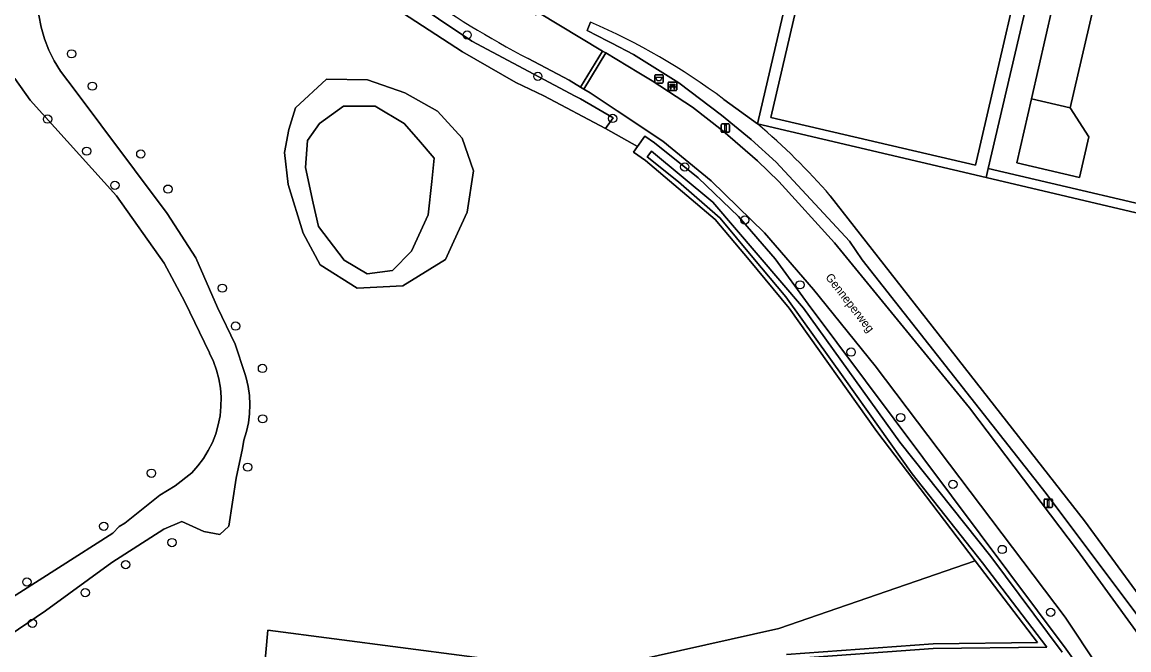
# Model space of a CAD drawing. Extents: x 160203 to 161530, y 379528 to 381797.
# Drawn here: x 160837.8 to 160969.1, y 381364.6 to 381439 of the extents above; entities that cross this region are included whole.
import ezdxf

# ---------------------------------------------------------------- set-up
doc = ezdxf.new("R2010")
doc.units = 0
for name, color, linetype in [('IMGEO_Afvalbak', 7, 'Continuous'), ('IMGEO_Bank', 7, 'Continuous'), ('IMGEO_Berm_groen', 7, 'Continuous'), ('IMGEO_Boom', 7, 'Continuous'), ('IMGEO_Grasland_agrarisch', 7, 'Continuous'), ('IMGEO_Grasland_overig', 7, 'Continuous'), ('IMGEO_Groenvoorziening', 7, 'Continuous'), ('IMGEO_Hek', 7, 'Continuous'), ('IMGEO_Lichtmast', 7, 'Continuous'), ('IMGEO_Loofbos', 7, 'Continuous'), ('IMGEO_Meer_plas_ven_vijver', 7, 'Continuous'), ('IMGEO_Oever', 7, 'Continuous'), ('IMGEO_Openbare_ruimte_label', 7, 'Continuous'), ('IMGEO_Rijbaan_lokaal_gesloten', 7, 'Continuous'), ('IMGEO_Waterloop', 7, 'Continuous')]:
    doc.layers.add(name, color=color, linetype=linetype)

msp = doc.modelspace()

# ---------------------------------------------------------------- linework, layer by layer
at = {"layer": 'IMGEO_Afvalbak'}
for p, q in [((160912.86, 381431.87), (160912.86, 381432.67)), ((160912.86, 381432.67), (160912.86, 381431.87)), ((160912.96, 381432.77), (160913.75, 381432.77)), ((160913.75, 381432.77), (160912.96, 381432.77)), ((160913.85, 381432.67), (160913.85, 381431.87)), ((160913.85, 381431.87), (160913.85, 381432.67)), ((160913.75, 381431.77), (160912.96, 381431.77)), ((160912.96, 381431.77), (160913.75, 381431.77))]:
    msp.add_line(p, q, dxfattribs=at)
msp.add_lwpolyline([(160913, 381432.49), (160913.71, 381432.49), (160913.56, 381432.02), (160913.15, 381432.02), (160913, 381432.49)], dxfattribs=at)
for centre, start, end in [((160912.96, 381432.67), 90, 180), ((160912.96, 381432.67), 90, 180), ((160912.96, 381431.87), 180, 270), ((160912.96, 381431.87), 180, 270), ((160913.75, 381432.67), 0, 90), ((160913.75, 381432.67), 360, 90), ((160913.75, 381431.87), 270, 0), ((160913.75, 381431.87), 270, 0)]:
    msp.add_arc(centre, 0.1, start, end, dxfattribs=at)
at = {"layer": 'IMGEO_Bank'}
for p, q in [((160914.53, 381431.88), (160915.37, 381431.88)), ((160915.37, 381431.88), (160914.53, 381431.88)), ((160914.46, 381430.96), (160914.46, 381431.8)), ((160914.46, 381431.8), (160914.46, 381430.96)), ((160915.38, 381430.89), (160914.54, 381430.89)), ((160914.54, 381430.89), (160915.38, 381430.89)), ((160915.16, 381431.28), (160914.76, 381431.28)), ((160914.77, 381431.39), (160914.77, 381431.5)), ((160914.81, 381431.5), (160914.81, 381431.39)), ((160915.1, 381431.5), (160914.82, 381431.5)), ((160914.82, 381431.39), (160915.1, 381431.39)), ((160915.11, 381431.39), (160915.11, 381431.5)), ((160915.15, 381431.5), (160915.15, 381431.39)), ((160915.46, 381431.81), (160915.46, 381430.97)), ((160915.46, 381430.97), (160915.46, 381431.81))]:
    msp.add_line(p, q, dxfattribs=at)
for points in [[(160914.71, 381431.28), (160914.56, 381431.28), (160914.68, 381431.39), (160914.76, 381431.39)], [(160914.76, 381431.5), (160914.68, 381431.5), (160914.68, 381431.66), (160915.24, 381431.66), (160915.24, 381431.5), (160915.16, 381431.5)], [(160914.76, 381431.28), (160914.76, 381431.07), (160914.71, 381431.07), (160914.71, 381431.28)], [(160915.16, 381431.39), (160915.24, 381431.39), (160915.35, 381431.28), (160915.21, 381431.28)], [(160915.21, 381431.28), (160915.21, 381431.07), (160915.16, 381431.07), (160915.16, 381431.28)]]:
    msp.add_lwpolyline(points, dxfattribs=at)
for centre, radius, start, end in [((160914.54, 381431.81), 0.0779, 92.4484, 184.2845), ((160914.54, 381431.81), 0.0779, 92.4484, 184.2845), ((160915.38, 381431.81), 0.0779, 2.4484, 94.2845), ((160915.38, 381431.81), 0.0779, 2.4484, 94.2845), ((160914.54, 381430.96), 0.0779, 182.4484, 274.2845), ((160914.54, 381430.96), 0.0779, 182.4484, 274.2845), ((160914.71, 381431.28), 0.00671, 2.8957, 87.1043), ((160914.76, 381431.5), 0.00671, 2.8957, 87.1043), ((160914.76, 381431.39), 0.00671, 272.8957, 357.1043), ((160914.76, 381431.28), 0.00671, 92.8957, 177.1043), ((160914.82, 381431.5), 0.00671, 92.8957, 177.1043), ((160914.82, 381431.39), 0.00671, 182.8957, 267.1043), ((160915.1, 381431.5), 0.00671, 2.8957, 87.1043), ((160915.1, 381431.39), 0.00671, 272.8957, 357.1043), ((160915.16, 381431.5), 0.00671, 92.8957, 177.1043), ((160915.16, 381431.39), 0.00671, 182.8957, 267.1043), ((160915.16, 381431.28), 0.00671, 2.8957, 87.1043), ((160915.21, 381431.28), 0.00671, 92.8957, 177.1043), ((160915.38, 381430.96), 0.0779, 272.4484, 4.2845), ((160915.38, 381430.96), 0.0779, 272.4484, 4.2845)]:
    msp.add_arc(centre, radius, start, end, dxfattribs=at)
at = {"layer": 'IMGEO_Berm_groen'}
for points in [[(160879.19, 381444.82), (160891.17, 381436.75), (160903.43, 381430.24), (160903.82, 381430.04), (160904.06, 381429.91), (160907.93, 381427.65), (160907.02, 381426.38), (160910.8, 381424.24), (160911.68, 381425.48), (160912.82, 381424.67), (160918, 381420.53), (160922.79, 381415.94), (160927.15, 381410.94), (160931.05, 381405.58), (160961.66, 381364.64), (160973.27, 381348.35)], [(160993, 381294.71), (160992.52, 381299.99), (160991.71, 381305.79), (160990.96, 381309.38), (160989.45, 381315.12), (160986.02, 381325.95), (160981.64, 381336.44), (160977.58, 381344.32), (160969.51, 381356.48), (160969.3, 381356.8), (160961.55, 381368.47), (160938.99, 381398.24), (160931.67, 381407.29), (160925.89, 381414), (160919.55, 381420.17), (160913.8, 381424.9), (160908.4, 381428.48), (160905.18, 381430.61), (160904.44, 381431.06), (160904.06, 381431.29), (160902.71, 381432.11), (160897.85, 381434.68)]]:
    msp.add_lwpolyline(points, dxfattribs=at)
msp.add_arc((160952.12, 381538.44), 117.1, 234.6618, 242.3896, dxfattribs=at)
at = {"layer": 'IMGEO_Boom'}
for centre in [(160890.61, 381437.48), (160843.69, 381435.24), (160846.15, 381431.41), (160898.99, 381432.57), (160840.84, 381427.5), (160907.87, 381427.58), (160845.47, 381423.7), (160851.9, 381423.37), (160916.42, 381421.83), (160848.83, 381419.65), (160855.12, 381419.2), (160923.54, 381415.53), (160930.09, 381407.85), (160861.57, 381407.46), (160863.14, 381402.96), (160936.15, 381399.88), (160866.33, 381397.94), (160942.03, 381392.12), (160866.36, 381391.97), (160853.16, 381385.52), (160864.58, 381386.24), (160948.22, 381384.2), (160847.51, 381379.23), (160855.6, 381377.3), (160954.07, 381376.48), (160850.11, 381374.68), (160838.39, 381372.62), (160845.31, 381371.36), (160959.82, 381369.03), (160839.05, 381367.73)]:
    msp.add_circle(centre, 0.489, dxfattribs=at)
at = {"layer": 'IMGEO_Grasland_agrarisch'}
for points in [[(160910.26, 381363.22), (160927.59, 381367.12), (160950.85, 381375.14), (160939.19, 381390.45), (160928.82, 381405.1), (160924.07, 381410.83), (160920.01, 381415.59), (160911.77, 381422.61), (160910.35, 381423.6), (160910.8, 381424.24), (160907.02, 381426.38), (160899.71, 381430.26), (160896.4, 381431.86), (160890.07, 381435.47), (160878.99, 381442.69)], [(160839.8, 381439.81), (160840.07, 381438.4), (160840.47, 381437.02), (160840.99, 381435.68), (160841.63, 381434.4), (160842.38, 381433.17), (160843.23, 381432.02), (160843.27, 381431.98), (160855.03, 381416.33), (160858.42, 381411.04), (160860.99, 381405.15), (160863.09, 381400.82), (160864.24, 381397.36), (160864.41, 381396.83), (160864.65, 381395.79), (160864.8, 381394.72), (160864.85, 381393.65), (160864.81, 381392.57), (160864.67, 381391.51), (160864.43, 381390.46), (160864.11, 381389.43), (160863.95, 381388.43), (160863.2, 381384.92), (160862.36, 381379.25), (160861.29, 381378.25), (160859.39, 381378.61), (160856.75, 381379.8), (160854.63, 381378.9), (160848.45, 381374.92), (160840.6, 381369.21), (160835.29, 381365.61)], [(160861.25, 381302.95), (160866.96, 381366.91), (160898.45, 381362.81)]]:
    msp.add_lwpolyline(points, dxfattribs=at)
msp.add_lwpolyline([(160877.58, 381407.45), (160873.19, 381410.22), (160871.16, 381413.96), (160869.36, 381419.74), (160868.94, 381423.53), (160869.45, 381426.26), (160870.24, 381428.85), (160873.93, 381432.22), (160878.78, 381432.17), (160883.22, 381430.6), (160887.1, 381428.43), (160890.01, 381425.24), (160891.35, 381421.36), (160890.61, 381416.46), (160889.04, 381413.04), (160888.04, 381410.87), (160882.99, 381407.73)], close=True, dxfattribs=at)
at = {"layer": 'IMGEO_Grasland_overig'}
msp.add_lwpolyline([(160887, 381511.65), (160943.21, 381498.82), (160926.61, 381427.71), (160950.89, 381422.03), (160966.02, 381487.2), (160966.83, 381487.02), (160967.33, 381489.23), (160968.8, 381488.86), (160972.12, 381488.02), (160973.76, 381493.85), (160983.38, 381535.9)], dxfattribs=at)
at = {"layer": 'IMGEO_Groenvoorziening'}
for points in [[(161150.15, 381500), (161152.01, 381508.05), (161153.71, 381515.38), (161141.46, 381516.56), (161125.47, 381518.11), (161084.45, 381527.5), (161000, 381546.84), (160993.38, 381548.35), (160986.4, 381549.95), (160985.95, 381548.01), (160992.01, 381546.65), (161000, 381544.86), (161087.73, 381524.31), (161123.21, 381516.23), (161094.22, 381388.52), (161000, 381410.48), (160979.1, 381415.39), (160952.41, 381421.66), (160952.15, 381420.57), (161000, 381409.32), (161095.64, 381387.19), (161107.24, 381437.71), (161118.58, 381435.09), (161134.28, 381431.47)], [(160968.89, 381457.97), (160964.18, 381459.05), (160957.55, 381429.91), (160962.15, 381428.85)], [(160957.55, 381429.91), (160955.81, 381422.31), (160963.25, 381420.56), (160964.36, 381425.4), (160962.15, 381428.85)]]:
    msp.add_lwpolyline(points, close=True, dxfattribs=at)
for points in [[(160932.03, 381500), (160941.58, 381497.82), (160925.05, 381426.94), (160952.15, 381420.57), (160952.41, 381421.66), (160967.65, 381486.84), (160966.83, 381487.02), (160966.02, 381487.2), (160950.89, 381422.03), (160926.61, 381427.71), (160943.21, 381498.82), (160887, 381511.65)], [(160899, 381440.18), (160906.67, 381435.56), (160907.05, 381435.34), (160910.97, 381432.97), (160912.55, 381432.02), (160917.33, 381428.91), (160920.95, 381426.1), (160925.03, 381422.57), (160927.57, 381420.1), (160934.19, 381412.82), (160950.18, 381393.29), (160963.01, 381376.35), (160971.37, 381364.8)], [(160974.18, 381363.23), (160959.28, 381383.1), (160937.45, 381410.82), (160935.96, 381413.05), (160927.26, 381422.41), (160924.3, 381425.07), (160920.79, 381427.97), (160915.73, 381431.81), (160910.35, 381435.18), (160907.77, 381436.49), (160907.29, 381436.74), (160904.84, 381437.99), (160905.25, 381439)], [(160835.69, 381370.18), (160848.57, 381378.42), (160849.33, 381379.2), (160850, 381379.59), (160854.15, 381382.93), (160855.98, 381384.02), (160857.95, 381385.57), (160858.68, 381386.39), (160859.33, 381387.27), (160859.9, 381388.2), (160860.39, 381389.18), (160860.79, 381390.2), (160861.09, 381391.26), (160861.3, 381392.33), (160861.41, 381393.42), (160861.43, 381394.52), (160861.34, 381395.61), (160861.16, 381396.69), (160860.89, 381397.75), (160860.52, 381398.78), (160860.06, 381399.77), (160860.05, 381399.8), (160857.13, 381405.83), (160854.69, 381410.43), (160849.02, 381418.42), (160838.77, 381429.76), (160836.95, 381432.33)]]:
    msp.add_lwpolyline(points, dxfattribs=at)
at = {"layer": 'IMGEO_Hek'}
for points in [[(160932.03, 381500), (160941.58, 381497.82), (160925.05, 381426.94)], [(160952.41, 381421.66), (160967.65, 381486.84)], [(160925.05, 381426.94), (160952.15, 381420.57)], [(160952.15, 381420.57), (160952.41, 381421.66)], [(160952.15, 381420.57), (161000, 381409.32)]]:
    msp.add_lwpolyline(points, dxfattribs=at)
at = {"layer": 'IMGEO_Lichtmast'}
for p, q in [((160920.74, 381426.04), (160920.74, 381426.83)), ((160920.74, 381426.83), (160920.74, 381426.04)), ((160920.84, 381426.93), (160921.63, 381426.93)), ((160921.63, 381426.93), (160920.84, 381426.93)), ((160921.73, 381426.83), (160921.73, 381426.04)), ((160921.73, 381426.04), (160921.73, 381426.83)), ((160921.63, 381425.94), (160920.84, 381425.94)), ((160920.84, 381425.94), (160921.63, 381425.94)), ((160959.03, 381381.56), (160959.03, 381382.36)), ((160959.03, 381382.36), (160959.03, 381381.56)), ((160959.13, 381382.46), (160959.92, 381382.46)), ((160959.92, 381382.46), (160959.13, 381382.46)), ((160960.02, 381382.36), (160960.02, 381381.56)), ((160960.02, 381381.56), (160960.02, 381382.36)), ((160959.92, 381381.46), (160959.13, 381381.46)), ((160959.13, 381381.46), (160959.92, 381381.46))]:
    msp.add_line(p, q, dxfattribs=at)
for points in [[(160921.16, 381426.81), (160921.31, 381426.81), (160921.31, 381426.06), (160921.16, 381426.06), (160921.16, 381426.81)], [(160959.45, 381382.34), (160959.6, 381382.34), (160959.6, 381381.59), (160959.45, 381381.59), (160959.45, 381382.34)]]:
    msp.add_lwpolyline(points, dxfattribs=at)
for centre, start, end in [((160920.84, 381426.83), 90, 180), ((160920.84, 381426.83), 90, 180), ((160921.63, 381426.83), 0, 90), ((160921.63, 381426.83), 360, 90), ((160920.84, 381426.04), 180, 270), ((160920.84, 381426.04), 180, 270), ((160921.63, 381426.04), 270, 0), ((160921.63, 381426.04), 270, 0), ((160959.13, 381382.36), 90, 180), ((160959.13, 381382.36), 90, 180), ((160959.92, 381382.36), 0, 90), ((160959.92, 381382.36), 360, 90), ((160959.13, 381381.56), 180, 270), ((160959.13, 381381.56), 180, 270), ((160959.92, 381381.56), 270, 0), ((160959.92, 381381.56), 270, 0)]:
    msp.add_arc(centre, 0.1, start, end, dxfattribs=at)
at = {"layer": 'IMGEO_Loofbos'}
for points in [[(160921.04, 381429.84), (160925.05, 381426.94), (160941.58, 381497.82)], [(161000, 381409.32), (160952.15, 381420.57), (160925.05, 381426.94)], [(160933.67, 381418.42), (160963.83, 381379.86), (160979.61, 381358.32), (160978.48, 381357.15), (160978.95, 381356.53), (160995.18, 381359.02), (161012.13, 381363.59), (161027.65, 381369.06), (161045.06, 381375.03), (161050.48, 381376.91), (161056.73, 381379.07)], [(160928.47, 381364.02), (160945.87, 381365.3), (160958.24, 381365.43), (160950.85, 381375.14), (160927.59, 381367.12), (160910.26, 381363.22)], [(160898.45, 381362.81), (160866.96, 381366.91), (160861.25, 381302.95)]]:
    msp.add_lwpolyline(points, dxfattribs=at)
for points in [[(160972.12, 381488.02), (160968.8, 381488.86), (160968.27, 381486.71), (160967.65, 381486.84), (160952.41, 381421.66), (160979.1, 381415.39), (160992.22, 381474.79), (160970.08, 381480.72)], [(160962.15, 381428.85), (160964.36, 381425.4), (160963.25, 381420.56), (160955.81, 381422.31), (160957.55, 381429.91), (160964.18, 381459.05), (160968.89, 381457.97)]]:
    msp.add_lwpolyline(points, close=True, dxfattribs=at)
for centre, radius, start, end in [((160875.24, 381369.02), 76.14, 53.014, 66.7814), ((160874.43, 381367.06), 78.4, 40.9191, 49.7892)]:
    msp.add_arc(centre, radius, start, end, dxfattribs=at)
at = {"layer": 'IMGEO_Meer_plas_ven_vijver'}
msp.add_lwpolyline([(160879.71, 381429.03), (160875.96, 381429.03), (160873.1, 381427), (160871.67, 381424.96), (160871.44, 381421.78), (160872.36, 381417.52), (160872.96, 381414.75), (160876.01, 381410.78), (160878.74, 381409.16), (160881.74, 381409.57), (160884, 381411.84), (160885.99, 381416.14), (160886.41, 381420.11), (160886.7, 381422.86), (160884.84, 381425.06), (160883.13, 381427)], close=True, dxfattribs=at)
at = {"layer": 'IMGEO_Oever'}
for points in [[(160878.78, 381432.17), (160873.93, 381432.22), (160870.24, 381428.85), (160869.45, 381426.26), (160868.94, 381423.53), (160869.36, 381419.74), (160871.16, 381413.96), (160873.19, 381410.22), (160877.58, 381407.45), (160882.99, 381407.73), (160888.04, 381410.87), (160889.04, 381413.04), (160890.61, 381416.46), (160891.35, 381421.36), (160890.01, 381425.24), (160887.1, 381428.43), (160883.22, 381430.6)], [(160879.71, 381429.03), (160883.13, 381427), (160884.84, 381425.06), (160886.7, 381422.86), (160886.41, 381420.11), (160885.99, 381416.14), (160884, 381411.84), (160881.74, 381409.57), (160878.74, 381409.16), (160876.01, 381410.78), (160872.96, 381414.75), (160872.36, 381417.52), (160871.44, 381421.78), (160871.67, 381424.96), (160873.1, 381427), (160875.96, 381429.03)]]:
    msp.add_lwpolyline(points, close=True, dxfattribs=at)
for points in [[(160973.27, 381348.35), (160961.66, 381364.64), (160931.05, 381405.58), (160927.15, 381410.94), (160922.79, 381415.94), (160918, 381420.53), (160912.82, 381424.67), (160911.68, 381425.48), (160910.8, 381424.24), (160910.35, 381423.6), (160911.77, 381422.61), (160920.01, 381415.59), (160924.07, 381410.83), (160928.82, 381405.1), (160939.19, 381390.45), (160950.85, 381375.14), (160958.24, 381365.43), (160945.87, 381365.3), (160928.47, 381364.02)], [(160928.52, 381363.46), (160945.89, 381364.73), (160959.37, 381364.88), (160951.73, 381374.91), (160943.39, 381385.43), (160935.42, 381396.67), (160928.41, 381406.42), (160924.48, 381411.11), (160920.6, 381415.74), (160915.68, 381420.05), (160911.97, 381423.01), (160912.14, 381423.26), (160912.48, 381423.7), (160919.75, 381417.67), (160930.52, 381405.07), (160941.92, 381389.22), (160952.73, 381375.64), (160961.2, 381364.31)]]:
    msp.add_lwpolyline(points, dxfattribs=at)
at = {"layer": 'IMGEO_Rijbaan_lokaal_gesloten'}
msp.add_lwpolyline([(160897.85, 381434.68), (160902.71, 381432.11), (160904.06, 381431.29), (160906.67, 381435.56), (160899, 381440.18), (160898.78, 381439.81), (160890.51, 381444.71), (160885.03, 381448.37), (160884, 381449.06), (160882.27, 381450.22), (160877.7, 381453.55), (160873.04, 381457.12), (160867.03, 381462.31)], dxfattribs=at)
for points in [[(160907.05, 381435.34), (160906.67, 381435.56), (160904.06, 381431.29), (160904.44, 381431.06)], [(160927.57, 381420.1), (160925.03, 381422.57), (160920.95, 381426.1), (160917.33, 381428.91), (160912.55, 381432.02), (160910.97, 381432.97), (160907.05, 381435.34), (160904.44, 381431.06), (160905.18, 381430.61), (160908.4, 381428.48), (160913.8, 381424.9), (160919.55, 381420.17), (160925.89, 381414), (160931.67, 381407.29), (160938.99, 381398.24), (160961.55, 381368.47), (160969.3, 381356.8), (160969.55, 381356.97), (160974.46, 381360.25), (160971.37, 381364.8), (160963.01, 381376.35), (160950.18, 381393.29), (160934.19, 381412.82)]]:
    msp.add_lwpolyline(points, close=True, dxfattribs=at)
msp.add_arc((160952.12, 381538.44), 117.1, 234.6618, 242.3896, dxfattribs=at)
at = {"layer": 'IMGEO_Waterloop'}
msp.add_lwpolyline([(160852, 381467.34), (160846.69, 381471.05), (160845.97, 381470.14), (160848.03, 381468.74), (160852.73, 381465.27), (160870.58, 381449.57), (160875.08, 381445.61), (160878.99, 381442.69), (160890.07, 381435.47), (160896.4, 381431.86), (160899.71, 381430.26), (160907.02, 381426.38), (160907.93, 381427.65), (160904.06, 381429.91), (160903.82, 381430.04), (160903.43, 381430.24), (160891.17, 381436.75), (160879.19, 381444.82), (160874.32, 381448.34), (160869.51, 381452.48), (160863.13, 381457.99)], close=True, dxfattribs=at)
for points in [[(160835.29, 381365.61), (160840.6, 381369.21), (160848.45, 381374.92), (160854.63, 381378.9), (160856.75, 381379.8), (160859.39, 381378.61), (160861.29, 381378.25), (160862.36, 381379.25), (160863.2, 381384.92), (160863.95, 381388.43), (160864.11, 381389.43), (160864.43, 381390.46), (160864.67, 381391.51), (160864.81, 381392.57), (160864.85, 381393.65), (160864.8, 381394.72), (160864.65, 381395.79), (160864.41, 381396.83), (160864.24, 381397.36), (160863.09, 381400.82), (160860.99, 381405.15), (160858.42, 381411.04), (160855.03, 381416.33), (160843.27, 381431.98), (160843.23, 381432.02), (160842.38, 381433.17), (160841.63, 381434.4), (160840.99, 381435.68), (160840.47, 381437.02), (160840.07, 381438.4), (160839.8, 381439.81)], [(160905.25, 381439), (160904.84, 381437.99), (160907.29, 381436.74), (160907.77, 381436.49), (160910.35, 381435.18), (160915.73, 381431.81), (160920.79, 381427.97), (160924.3, 381425.07), (160927.26, 381422.41), (160935.96, 381413.05), (160937.45, 381410.82), (160959.28, 381383.1), (160974.18, 381363.23), (160978.48, 381357.15), (160979.61, 381358.32), (160963.83, 381379.86)], [(160836.95, 381432.33), (160838.77, 381429.76), (160849.02, 381418.42), (160854.69, 381410.43), (160857.13, 381405.83), (160860.05, 381399.8), (160860.06, 381399.77), (160860.52, 381398.78), (160860.89, 381397.75), (160861.16, 381396.69), (160861.34, 381395.61), (160861.43, 381394.52), (160861.41, 381393.42), (160861.3, 381392.33), (160861.09, 381391.26), (160860.79, 381390.2), (160860.39, 381389.18), (160859.9, 381388.2), (160859.33, 381387.27), (160858.68, 381386.39), (160857.95, 381385.57), (160855.98, 381384.02), (160854.15, 381382.93), (160850, 381379.59), (160849.33, 381379.2), (160848.57, 381378.42), (160835.69, 381370.18)], [(160925.05, 381426.94), (160921.04, 381429.84)], [(160961.2, 381364.31), (160952.73, 381375.64), (160941.92, 381389.22), (160930.52, 381405.07), (160919.75, 381417.67), (160912.48, 381423.7), (160912.14, 381423.26), (160911.97, 381423.01), (160915.68, 381420.05), (160920.6, 381415.74), (160924.48, 381411.11), (160928.41, 381406.42), (160935.42, 381396.67), (160943.39, 381385.43), (160951.73, 381374.91), (160959.37, 381364.88), (160945.89, 381364.73), (160928.52, 381363.46)], [(160963.83, 381379.86), (160933.67, 381418.42)]]:
    msp.add_lwpolyline(points, dxfattribs=at)
for centre, radius, start, end in [((160875.24, 381369.02), 76.14, 53.014, 66.7814), ((160874.43, 381367.06), 78.4, 40.9191, 49.7892)]:
    msp.add_arc(centre, radius, start, end, dxfattribs=at)

# ---------------------------------------------------------------- texts
at = {"layer": 'IMGEO_Openbare_ruimte_label'}
msp.add_text('Genneperweg', height=1, rotation=307.8097, dxfattribs=at).set_placement((160933.05, 381408.74))

doc.saveas('drawing.dxf')
